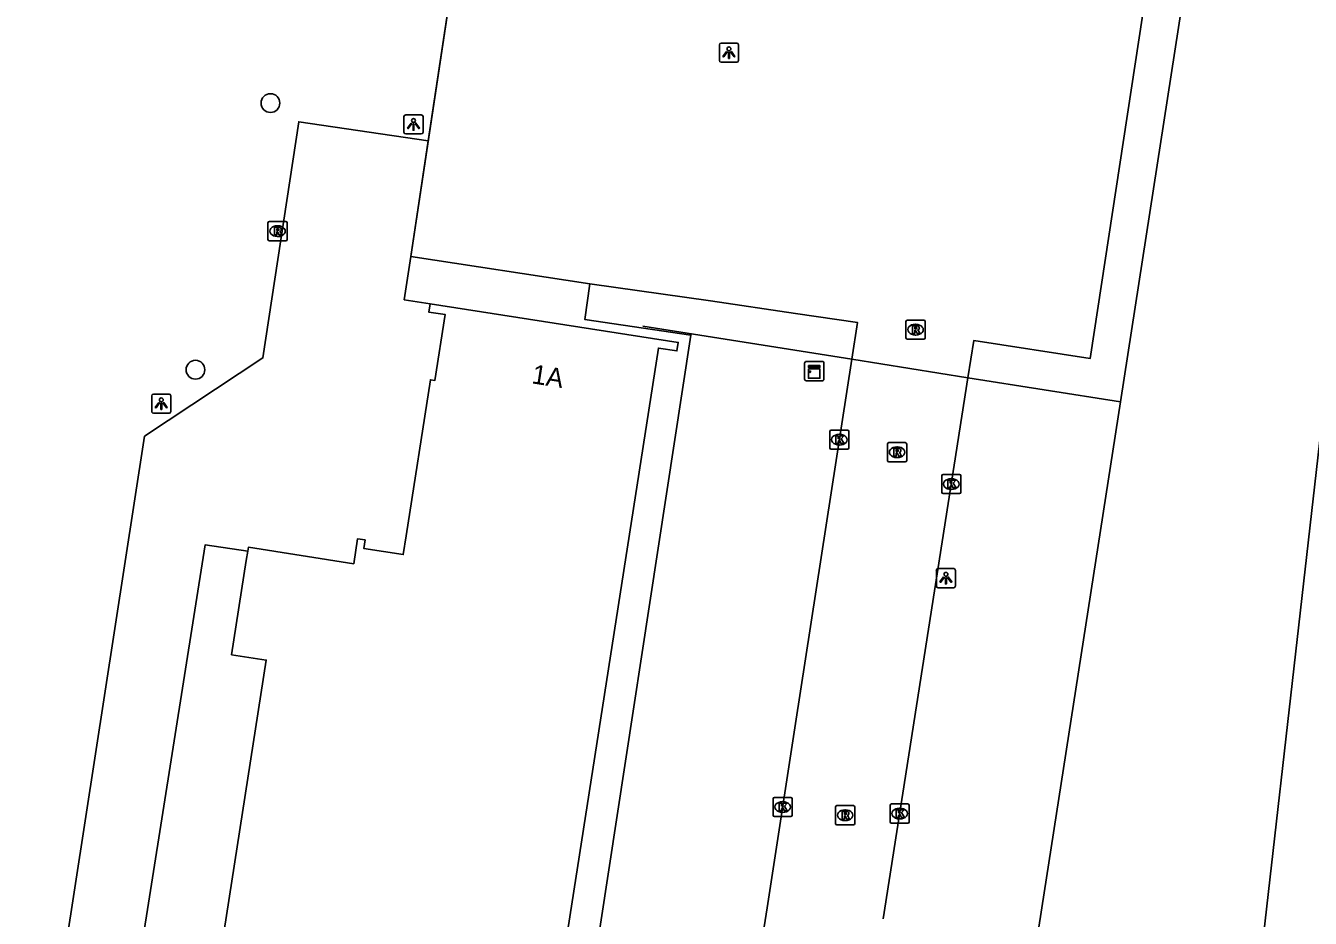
# Model space of a CAD drawing. Extents: x 161094 to 161705, y 379509 to 380907.
# Drawn here: x 161459.9 to 161526.8, y 380785 to 380831.5 of the extents above; entities that cross this region are included whole.
import ezdxf

# ---------------------------------------------------------------- set-up
doc = ezdxf.new("R2010")
doc.units = 0
for name, color, linetype in [('IMGEO_Boom', 7, 'Continuous'), ('IMGEO_Grasland_overig', 7, 'Continuous'), ('IMGEO_Groenvoorziening', 7, 'Continuous'), ('IMGEO_Hek', 7, 'Continuous'), ('IMGEO_Kast', 7, 'Continuous'), ('IMGEO_Kolk', 7, 'Continuous'), ('IMGEO_Lichtpunt', 7, 'Continuous'), ('IMGEO_Pand', 7, 'Continuous'), ('IMGEO_Pand_nummerreeks', 7, 'Continuous'), ('IMGEO_Pand_vergunning_verleend', 7, 'Continuous'), ('IMGEO_Rijbaan_lokaal_open', 7, 'Continuous'), ('IMGEO_Rioolput', 7, 'Continuous')]:
    doc.layers.add(name, color=color, linetype=linetype)

msp = doc.modelspace()

# ---------------------------------------------------------------- linework, layer by layer
at = {"layer": 'IMGEO_Boom'}
for centre in [(161472.664, 380827.464), (161468.76, 380813.578)]:
    msp.add_circle(centre, 0.489, dxfattribs=at)
at = {"layer": 'IMGEO_Grasland_overig'}
for points in [[(161516.913, 380811.905), (161521.086, 380838.815), (161601.047, 380825.222), (161596.254, 380793.968)], [(161489.288, 380818.046), (161489.039, 380816.188), (161494.551, 380815.379), (161489.009, 380779.266), (161488.373, 380779.362)], [(161516.913, 380811.905), (161512.549, 380783.771)]]:
    msp.add_lwpolyline(points, dxfattribs=at)
at = {"layer": 'IMGEO_Groenvoorziening'}
msp.add_lwpolyline([(161508.972, 380813.163), (161516.913, 380811.905)], dxfattribs=at)
at = {"layer": 'IMGEO_Hek'}
for points in [[(161483.811, 380844.913), (161479.969, 380819.467)], [(161479.969, 380819.467), (161479.63, 380817.221), (161480.975, 380817.011)], [(161492.055, 380815.844), (161502.924, 380814.122)], [(161502.924, 380814.122), (161508.972, 380813.163)]]:
    msp.add_lwpolyline(points, dxfattribs=at)
at = {"layer": 'IMGEO_Kast'}
for p, q in [((161500.475, 380813.08), (161500.475, 380813.921)), ((161500.475, 380813.921), (161500.475, 380813.08)), ((161500.55, 380814.005), (161501.391, 380814.005)), ((161501.391, 380814.005), (161500.55, 380814.005)), ((161501.475, 380813.93), (161501.475, 380813.089)), ((161501.475, 380813.089), (161501.475, 380813.93)), ((161501.4, 380813.005), (161500.559, 380813.005)), ((161500.559, 380813.005), (161501.4, 380813.005))]:
    msp.add_line(p, q, dxfattribs=at)
for points in [[(161500.67, 380813.795), (161501.27, 380813.795), (161501.27, 380813.71), (161500.67, 380813.71), (161500.67, 380813.795)], [(161500.67, 380813.62), (161501.27, 380813.62), (161501.27, 380813.131), (161500.67, 380813.131), (161500.67, 380813.62)]]:
    msp.add_lwpolyline(points, dxfattribs=at)
msp.add_circle((161500.754, 380813.469), 0.0377, dxfattribs=at)
for centre, start, end in [((161500.553, 380813.927), 92.4484, 184.28452), ((161500.553, 380813.927), 92.4484, 184.28452), ((161501.397, 380813.927), 2.4484, 94.28452), ((161501.397, 380813.927), 2.4484, 94.28452), ((161500.553, 380813.083), 182.4484, 274.28452), ((161500.553, 380813.083), 182.4484, 274.28452), ((161501.397, 380813.083), 272.4484, 4.28452), ((161501.397, 380813.083), 272.4484, 4.28452)]:
    msp.add_arc(centre, 0.0779, start, end, dxfattribs=at)
at = {"layer": 'IMGEO_Kolk'}
for p, q in [((161501.781, 380809.508), (161501.781, 380810.36)), ((161501.856, 380810.434), (161502.708, 380810.434)), ((161502.269, 380810.214), (161502.294, 380810.214)), ((161502.782, 380810.36), (161502.782, 380809.508)), ((161502.708, 380809.434), (161501.856, 380809.434)), ((161502.292, 380809.654), (161502.267, 380809.654)), ((161507.61, 380807.198), (161507.61, 380808.05)), ((161507.685, 380808.124), (161508.537, 380808.124)), ((161508.611, 380808.05), (161508.611, 380807.198)), ((161508.098, 380807.904), (161508.123, 380807.904)), ((161508.537, 380807.124), (161507.685, 380807.124)), ((161508.121, 380807.344), (161508.096, 380807.344)), ((161498.828, 380790.378), (161498.828, 380791.23)), ((161498.903, 380791.304), (161499.755, 380791.304)), ((161499.316, 380791.084), (161499.341, 380791.084)), ((161499.829, 380791.23), (161499.829, 380790.378)), ((161504.921, 380790.037), (161504.921, 380790.889)), ((161504.996, 380790.963), (161505.848, 380790.963)), ((161505.409, 380790.743), (161505.434, 380790.743)), ((161505.922, 380790.889), (161505.922, 380790.037)), ((161499.755, 380790.304), (161498.903, 380790.304)), ((161499.339, 380790.524), (161499.314, 380790.524)), ((161505.432, 380790.183), (161505.407, 380790.183)), ((161505.848, 380789.963), (161504.996, 380789.963))]:
    msp.add_line(p, q, dxfattribs=at)
for points in [[(161501.781, 380809.508), (161501.781, 380810.36)], [(161501.856, 380810.434), (161502.708, 380810.434)], [(161502.102, 380810.134), (161502.225, 380810.134), (161502.225, 380809.983), (161502.355, 380810.134), (161502.519, 380810.134), (161502.373, 380809.983), (161502.526, 380809.734), (161502.374, 380809.734), (161502.289, 380809.898), (161502.225, 380809.831), (161502.225, 380809.734), (161502.102, 380809.734), (161502.102, 380810.134)], [(161502.782, 380810.36), (161502.782, 380809.508)], [(161502.708, 380809.434), (161501.856, 380809.434)], [(161507.61, 380807.198), (161507.61, 380808.05)], [(161507.685, 380808.124), (161508.537, 380808.124)], [(161508.611, 380808.05), (161508.611, 380807.198)], [(161507.931, 380807.824), (161508.054, 380807.824), (161508.054, 380807.673), (161508.184, 380807.824), (161508.348, 380807.824), (161508.202, 380807.673), (161508.355, 380807.424), (161508.203, 380807.424), (161508.118, 380807.588), (161508.054, 380807.521), (161508.054, 380807.424), (161507.931, 380807.424), (161507.931, 380807.824)], [(161508.537, 380807.124), (161507.685, 380807.124)], [(161498.828, 380790.378), (161498.828, 380791.23)], [(161498.903, 380791.304), (161499.755, 380791.304)], [(161499.149, 380791.004), (161499.272, 380791.004), (161499.272, 380790.853), (161499.402, 380791.004), (161499.566, 380791.004), (161499.42, 380790.853), (161499.573, 380790.604), (161499.421, 380790.604), (161499.336, 380790.768), (161499.272, 380790.701), (161499.272, 380790.604), (161499.149, 380790.604), (161499.149, 380791.004)], [(161499.829, 380791.23), (161499.829, 380790.378)], [(161504.921, 380790.037), (161504.921, 380790.889)], [(161504.996, 380790.963), (161505.848, 380790.963)], [(161505.242, 380790.663), (161505.365, 380790.663), (161505.365, 380790.512), (161505.495, 380790.663), (161505.659, 380790.663), (161505.513, 380790.512), (161505.666, 380790.263), (161505.514, 380790.263), (161505.429, 380790.427), (161505.365, 380790.36), (161505.365, 380790.263), (161505.242, 380790.263), (161505.242, 380790.663)], [(161505.922, 380790.889), (161505.922, 380790.037)], [(161499.755, 380790.304), (161498.903, 380790.304)], [(161505.848, 380789.963), (161504.996, 380789.963)]]:
    msp.add_lwpolyline(points, dxfattribs=at)
for centre, start, end in [((161501.858, 380810.358), 91.55205, 178.44795), ((161501.858, 380810.358), 91.55205, 178.44795), ((161502.706, 380810.358), 1.55205, 88.44795), ((161502.706, 380810.358), 1.55205, 88.44795), ((161501.858, 380809.51), 181.55205, 268.44795), ((161501.858, 380809.51), 181.55205, 268.44795), ((161502.706, 380809.51), 271.55205, 358.44795), ((161502.706, 380809.51), 271.55205, 358.44795), ((161507.687, 380808.048), 91.55205, 178.44795), ((161507.687, 380808.048), 91.55205, 178.44795), ((161508.535, 380808.048), 1.55205, 88.44795), ((161508.535, 380808.048), 1.55205, 88.44795), ((161507.687, 380807.2), 181.55205, 268.44795), ((161507.687, 380807.2), 181.55205, 268.44795), ((161508.535, 380807.2), 271.55205, 358.44795), ((161508.535, 380807.2), 271.55205, 358.44795), ((161498.905, 380791.228), 91.55205, 178.44795), ((161498.905, 380791.228), 91.55205, 178.44795), ((161499.753, 380791.228), 1.55205, 88.44795), ((161499.753, 380791.228), 1.55205, 88.44795), ((161504.998, 380790.887), 91.55205, 178.44795), ((161504.998, 380790.887), 91.55205, 178.44795), ((161505.846, 380790.887), 1.55205, 88.44795), ((161505.846, 380790.887), 1.55205, 88.44795), ((161498.905, 380790.38), 181.55205, 268.44795), ((161498.905, 380790.38), 181.55205, 268.44795), ((161499.753, 380790.38), 271.55205, 358.44795), ((161499.753, 380790.38), 271.55205, 358.44795), ((161504.998, 380790.039), 181.55205, 268.44795), ((161504.998, 380790.039), 181.55205, 268.44795), ((161505.846, 380790.039), 271.55205, 358.44795), ((161505.846, 380790.039), 271.55205, 358.44795)]:
    msp.add_arc(centre, 0.0765, start, end, dxfattribs=at)
for centre, major_axis, ratio, start_param, end_param in [((161502.268, 380809.934), (-0.387, 0.002), 0.722429, 4.712389, 7.853982), ((161502.293, 380809.934), (-0.39, 0.002), 0.717154, 1.570796, 4.712389), ((161508.097, 380807.624), (-0.387, 0.002), 0.722429, 4.712389, 7.853982), ((161508.122, 380807.624), (-0.39, 0.002), 0.717154, 1.570796, 4.712389), ((161499.315, 380790.804), (-0.387, 0.002), 0.722429, 4.712389, 7.853982), ((161499.34, 380790.804), (-0.39, 0.002), 0.717154, 1.570796, 4.712389), ((161505.408, 380790.463), (-0.387, 0.002), 0.722429, 4.712389, 7.853982), ((161505.433, 380790.463), (-0.39, 0.002), 0.717154, 1.570796, 4.712389)]:
    msp.add_ellipse(centre, major_axis=major_axis, ratio=ratio, start_param=start_param, end_param=end_param, dxfattribs=at)
at = {"layer": 'IMGEO_Lichtpunt'}
for p, q in [((161496.036, 380830.492), (161496.036, 380829.685)), ((161496.036, 380830.492), (161496.036, 380829.685)), ((161496.938, 380830.587), (161496.13, 380830.587)), ((161496.938, 380830.587), (161496.13, 380830.587)), ((161497.032, 380829.685), (161497.032, 380830.492)), ((161497.032, 380829.685), (161497.032, 380830.492)), ((161496.13, 380829.591), (161496.938, 380829.591)), ((161496.13, 380829.591), (161496.938, 380829.591)), ((161479.614, 380826.759), (161479.614, 380825.952)), ((161479.614, 380826.759), (161479.614, 380825.952)), ((161480.516, 380826.854), (161479.708, 380826.854)), ((161480.516, 380826.854), (161479.708, 380826.854)), ((161480.61, 380825.952), (161480.61, 380826.759)), ((161480.61, 380825.952), (161480.61, 380826.759)), ((161479.708, 380825.858), (161480.516, 380825.858)), ((161479.708, 380825.858), (161480.516, 380825.858)), ((161466.483, 380812.212), (161466.483, 380811.405)), ((161466.483, 380812.212), (161466.483, 380811.405)), ((161467.385, 380812.307), (161466.577, 380812.307)), ((161467.385, 380812.307), (161466.577, 380812.307)), ((161467.479, 380811.405), (161467.479, 380812.212)), ((161467.479, 380811.405), (161467.479, 380812.212)), ((161466.577, 380811.311), (161467.385, 380811.311)), ((161466.577, 380811.311), (161467.385, 380811.311)), ((161507.331, 380803.126), (161507.331, 380802.319)), ((161507.331, 380803.126), (161507.331, 380802.319)), ((161508.233, 380803.221), (161507.425, 380803.221)), ((161508.233, 380803.221), (161507.425, 380803.221)), ((161508.327, 380802.319), (161508.327, 380803.126)), ((161508.327, 380802.319), (161508.327, 380803.126)), ((161507.425, 380802.225), (161508.233, 380802.225)), ((161507.425, 380802.225), (161508.233, 380802.225))]:
    msp.add_line(p, q, dxfattribs=at)
for points in [[(161496.41, 380830.156), (161496.449, 380830.128), (161496.261, 380829.866), (161496.223, 380829.893), (161496.41, 380830.156)], [(161496.512, 380830.108), (161496.559, 380830.108), (161496.559, 380829.786), (161496.512, 380829.786), (161496.512, 380830.108)], [(161496.622, 380830.128), (161496.66, 380830.155), (161496.847, 380829.893), (161496.808, 380829.865), (161496.622, 380830.128)], [(161479.988, 380826.423), (161480.027, 380826.395), (161479.839, 380826.133), (161479.801, 380826.16), (161479.988, 380826.423)], [(161480.09, 380826.375), (161480.137, 380826.375), (161480.137, 380826.053), (161480.09, 380826.053), (161480.09, 380826.375)], [(161480.2, 380826.395), (161480.238, 380826.422), (161480.425, 380826.16), (161480.386, 380826.132), (161480.2, 380826.395)], [(161466.857, 380811.876), (161466.896, 380811.848), (161466.708, 380811.586), (161466.67, 380811.613), (161466.857, 380811.876)], [(161466.959, 380811.828), (161467.006, 380811.828), (161467.006, 380811.506), (161466.959, 380811.506), (161466.959, 380811.828)], [(161467.069, 380811.848), (161467.107, 380811.875), (161467.294, 380811.613), (161467.255, 380811.585), (161467.069, 380811.848)], [(161507.705, 380802.79), (161507.744, 380802.762), (161507.556, 380802.5), (161507.518, 380802.527), (161507.705, 380802.79)], [(161507.807, 380802.742), (161507.854, 380802.742), (161507.854, 380802.42), (161507.807, 380802.42), (161507.807, 380802.742)], [(161507.917, 380802.762), (161507.955, 380802.789), (161508.142, 380802.527), (161508.103, 380802.499), (161507.917, 380802.762)]]:
    msp.add_lwpolyline(points, dxfattribs=at)
for centre in [(161496.535, 380830.29), (161480.113, 380826.557), (161466.982, 380812.01), (161507.83, 380802.924)]:
    msp.add_circle(centre, 0.0994, dxfattribs=at)
for centre, start, end in [((161496.13, 380830.492), 90, 180), ((161496.13, 380830.492), 90, 180), ((161496.938, 380830.492), 0, 90), ((161496.938, 380830.492), 0, 90), ((161496.13, 380829.685), 180, 270), ((161496.13, 380829.685), 180, 270), ((161496.938, 380829.685), 270, 0), ((161496.938, 380829.685), 270, 360), ((161479.708, 380826.759), 90, 180), ((161479.708, 380826.759), 90, 180), ((161480.516, 380826.759), 0, 90), ((161480.516, 380826.759), 0, 90), ((161479.708, 380825.952), 180, 270), ((161479.708, 380825.952), 180, 270), ((161480.516, 380825.952), 270, 0), ((161480.516, 380825.952), 270, 360), ((161466.577, 380812.212), 90, 180), ((161466.577, 380812.212), 90, 180), ((161467.385, 380812.212), 0, 90), ((161467.385, 380812.212), 0, 90), ((161466.577, 380811.405), 180, 270), ((161466.577, 380811.405), 180, 270), ((161467.385, 380811.405), 270, 0), ((161467.385, 380811.405), 270, 360), ((161507.425, 380803.126), 90, 180), ((161507.425, 380803.126), 90, 180), ((161508.233, 380803.126), 0, 90), ((161508.233, 380803.126), 0, 90), ((161507.425, 380802.319), 180, 270), ((161507.425, 380802.319), 180, 270), ((161508.233, 380802.319), 270, 0), ((161508.233, 380802.319), 270, 360)]:
    msp.add_arc(centre, 0.0946, start, end, dxfattribs=at)
at = {"layer": 'IMGEO_Pand'}
for points in [[(161471.482, 380804.13), (161471.513, 380804.33), (161476.997, 380803.476), (161477.199, 380804.771), (161477.588, 380804.71), (161477.52, 380804.268), (161479.576, 380803.948), (161479.729, 380804.929), (161480.995, 380813.059), (161481.228, 380813.023), (161481.762, 380816.45), (161480.909, 380816.583), (161480.975, 380817.011)], [(161488.373, 380779.362), (161488.443, 380779.809), (161487.449, 380779.964), (161492.859, 380814.704), (161493.827, 380814.553), (161493.896, 380814.998), (161480.975, 380817.011)], [(161479.562, 380780.734), (161476.814, 380781.162), (161476.589, 380779.719), (161477.75, 380779.538), (161477.168, 380775.804), (161467.337, 380777.335), (161467.919, 380781.072), (161469.697, 380780.795), (161472.447, 380798.453), (161470.641, 380798.735), (161471.406, 380803.645), (161471.482, 380804.13)]]:
    msp.add_lwpolyline(points, dxfattribs=at)
at = {"layer": 'IMGEO_Pand_vergunning_verleend'}
msp.add_lwpolyline([(161523.106, 380773.117), (161527.36, 380810.515), (161542.271, 380808.163), (161541.03, 380800.291), (161538.939, 380800.621), (161535.649, 380771.69), (161523.106, 380773.117)], dxfattribs=at)
at = {"layer": 'IMGEO_Rijbaan_lokaal_open'}
for points in [[(161514.151, 380847.032), (161513.175, 380840.578), (161519.233, 380839.628), (161515.332, 380814.159), (161509.275, 380815.096), (161508.972, 380813.163)], [(161480.879, 380825.492), (161483.811, 380844.913)], [(161480.879, 380825.492), (161474.136, 380826.491), (161472.272, 380814.194), (161466.099, 380810.112), (161459.922, 380770.043)], [(161479.969, 380819.467), (161480.879, 380825.492)], [(161480.975, 380817.011), (161479.63, 380817.221), (161479.969, 380819.467)], [(161489.288, 380818.046), (161479.969, 380819.467)], [(161502.924, 380814.122), (161503.22, 380816.04), (161500, 380816.511), (161495.578, 380817.158), (161489.288, 380818.046)], [(161502.924, 380814.122), (161500, 380795.153), (161498.521, 380785.559), (161496.279, 380771.409)], [(161508.972, 380813.163), (161502.924, 380814.122)], [(161504.561, 380784.974), (161508.972, 380813.163)], [(161464.799, 380776.254), (161469.257, 380804.457), (161471.482, 380804.13)]]:
    msp.add_lwpolyline(points, dxfattribs=at)
at = {"layer": 'IMGEO_Rioolput'}
for p, q in [((161472.535, 380820.368), (161472.535, 380821.22)), ((161472.61, 380821.294), (161473.462, 380821.294)), ((161473.023, 380821.074), (161473.048, 380821.074)), ((161473.536, 380821.22), (161473.536, 380820.368)), ((161473.462, 380820.294), (161472.61, 380820.294)), ((161473.046, 380820.514), (161473.021, 380820.514)), ((161505.75, 380815.238), (161505.75, 380816.09)), ((161505.825, 380816.164), (161506.677, 380816.164)), ((161506.751, 380816.09), (161506.751, 380815.238)), ((161506.261, 380815.384), (161506.236, 380815.384)), ((161506.238, 380815.944), (161506.263, 380815.944)), ((161506.677, 380815.164), (161505.825, 380815.164)), ((161504.787, 380808.856), (161504.787, 380809.708)), ((161504.862, 380809.782), (161505.714, 380809.782)), ((161505.275, 380809.562), (161505.3, 380809.562)), ((161505.788, 380809.708), (161505.788, 380808.856)), ((161505.714, 380808.782), (161504.862, 380808.782)), ((161505.298, 380809.002), (161505.273, 380809.002)), ((161502.083, 380789.95), (161502.083, 380790.802)), ((161502.158, 380790.876), (161503.01, 380790.876)), ((161502.571, 380790.656), (161502.596, 380790.656)), ((161503.084, 380790.802), (161503.084, 380789.95)), ((161502.594, 380790.096), (161502.569, 380790.096)), ((161503.01, 380789.876), (161502.158, 380789.876))]:
    msp.add_line(p, q, dxfattribs=at)
for points in [[(161472.535, 380820.368), (161472.535, 380821.22)], [(161472.61, 380821.294), (161473.462, 380821.294)], [(161473.124, 380820.992), (161472.872, 380820.994), (161472.872, 380820.594)], [(161472.872, 380820.594), (161472.996, 380820.594), (161472.996, 380820.756), (161473.007, 380820.756)], [(161473.05, 380820.913), (161472.996, 380820.913), (161472.996, 380820.832)], [(161472.996, 380820.832), (161473.048, 380820.832)], [(161473.536, 380821.22), (161473.536, 380820.368)], [(161473.462, 380820.294), (161472.61, 380820.294)], [(161473.054, 380820.727), (161473.125, 380820.594), (161473.265, 380820.594), (161473.2, 380820.72)], [(161505.75, 380815.238), (161505.75, 380816.09)], [(161505.825, 380816.164), (161506.677, 380816.164)], [(161506.751, 380816.09), (161506.751, 380815.238)], [(161506.339, 380815.862), (161506.087, 380815.864), (161506.087, 380815.464)], [(161506.087, 380815.464), (161506.211, 380815.464), (161506.211, 380815.626), (161506.222, 380815.626)], [(161506.265, 380815.783), (161506.211, 380815.783), (161506.211, 380815.702)], [(161506.211, 380815.702), (161506.263, 380815.702)], [(161506.269, 380815.597), (161506.34, 380815.464), (161506.48, 380815.464), (161506.415, 380815.59)], [(161506.677, 380815.164), (161505.825, 380815.164)], [(161504.787, 380808.856), (161504.787, 380809.708)], [(161504.862, 380809.782), (161505.714, 380809.782)], [(161505.376, 380809.48), (161505.124, 380809.482), (161505.124, 380809.082)], [(161505.302, 380809.401), (161505.248, 380809.401), (161505.248, 380809.32)], [(161505.788, 380809.708), (161505.788, 380808.856)], [(161505.714, 380808.782), (161504.862, 380808.782)], [(161505.124, 380809.082), (161505.248, 380809.082), (161505.248, 380809.244), (161505.259, 380809.244)], [(161505.248, 380809.32), (161505.3, 380809.32)], [(161505.306, 380809.215), (161505.377, 380809.082), (161505.517, 380809.082), (161505.452, 380809.208)], [(161502.083, 380789.95), (161502.083, 380790.802)], [(161502.158, 380790.876), (161503.01, 380790.876)], [(161503.084, 380790.802), (161503.084, 380789.95)], [(161502.672, 380790.574), (161502.42, 380790.576), (161502.42, 380790.176)], [(161502.42, 380790.176), (161502.544, 380790.176), (161502.544, 380790.338), (161502.555, 380790.338)], [(161502.598, 380790.495), (161502.544, 380790.495), (161502.544, 380790.414)], [(161502.544, 380790.414), (161502.596, 380790.414)], [(161502.602, 380790.309), (161502.673, 380790.176), (161502.813, 380790.176), (161502.748, 380790.302)], [(161503.01, 380789.876), (161502.158, 380789.876)]]:
    msp.add_lwpolyline(points, dxfattribs=at)
for centre, radius, start, end in [((161472.612, 380821.218), 0.0765, 91.55205, 178.44795), ((161472.612, 380821.218), 0.0765, 91.55205, 178.44795), ((161473.006, 380820.703), 0.0533, 26.02933, 88.69889), ((161473.032, 380821.021), 0.19, 274.7715, 282.96867), ((161473.056, 380820.817), 0.0964, 77.00612, 93.18647), ((161473.07, 380820.874), 0.0378, 276.66336, 79.67722), ((161473.123, 380820.882), 0.109, 350.36119, 89.41601), ((161473.121, 380820.882), 0.112, 277.58423, 350.98172), ((161473.105, 380820.667), 0.108, 29.51342, 73.79051), ((161473.46, 380821.218), 0.0765, 1.55205, 88.44795), ((161473.46, 380821.218), 0.0765, 1.55205, 88.44795), ((161472.612, 380820.37), 0.0765, 181.55205, 268.44795), ((161472.612, 380820.37), 0.0765, 181.55205, 268.44795), ((161473.46, 380820.37), 0.0765, 271.55205, 358.44795), ((161473.46, 380820.37), 0.0765, 271.55205, 358.44795), ((161505.827, 380816.088), 0.0765, 91.55205, 178.44795), ((161505.827, 380816.088), 0.0765, 91.55205, 178.44795), ((161506.675, 380816.088), 0.0765, 1.55205, 88.44795), ((161506.675, 380816.088), 0.0765, 1.55205, 88.44795), ((161506.221, 380815.573), 0.0533, 26.02933, 88.69889), ((161506.247, 380815.891), 0.19, 274.7715, 282.96867), ((161506.271, 380815.687), 0.0964, 77.00612, 93.18647), ((161506.285, 380815.744), 0.0378, 276.66336, 79.67722), ((161506.338, 380815.752), 0.109, 350.36119, 89.41601), ((161506.336, 380815.752), 0.112, 277.58423, 350.98172), ((161506.32, 380815.537), 0.108, 29.51342, 73.79051), ((161505.827, 380815.24), 0.0765, 181.55205, 268.44795), ((161505.827, 380815.24), 0.0765, 181.55205, 268.44795), ((161506.675, 380815.24), 0.0765, 271.55205, 358.44795), ((161506.675, 380815.24), 0.0765, 271.55205, 358.44795), ((161504.864, 380809.706), 0.0765, 91.55205, 178.44795), ((161504.864, 380809.706), 0.0765, 91.55205, 178.44795), ((161505.308, 380809.305), 0.0964, 77.00612, 93.18647), ((161505.322, 380809.362), 0.0378, 276.66336, 79.67722), ((161505.375, 380809.37), 0.109, 350.36119, 89.41601), ((161505.712, 380809.706), 0.0765, 1.55205, 88.44795), ((161505.712, 380809.706), 0.0765, 1.55205, 88.44795), ((161504.864, 380808.858), 0.0765, 181.55205, 268.44795), ((161504.864, 380808.858), 0.0765, 181.55205, 268.44795), ((161505.258, 380809.191), 0.0533, 26.02933, 88.69889), ((161505.284, 380809.509), 0.19, 274.7715, 282.96867), ((161505.373, 380809.37), 0.112, 277.58423, 350.98172), ((161505.357, 380809.155), 0.108, 29.51342, 73.79051), ((161505.712, 380808.858), 0.0765, 271.55205, 358.44795), ((161505.712, 380808.858), 0.0765, 271.55205, 358.44795), ((161502.16, 380790.8), 0.0765, 91.55205, 178.44795), ((161502.16, 380790.8), 0.0765, 91.55205, 178.44795), ((161503.008, 380790.8), 0.0765, 1.55205, 88.44795), ((161503.008, 380790.8), 0.0765, 1.55205, 88.44795), ((161502.554, 380790.285), 0.0533, 26.02933, 88.69889), ((161502.58, 380790.603), 0.19, 274.7715, 282.96867), ((161502.604, 380790.399), 0.0964, 77.00612, 93.18647), ((161502.618, 380790.456), 0.0378, 276.66336, 79.67722), ((161502.671, 380790.464), 0.109, 350.36119, 89.41601), ((161502.669, 380790.464), 0.112, 277.58423, 350.98172), ((161502.653, 380790.249), 0.108, 29.51342, 73.79051), ((161502.16, 380789.952), 0.0765, 181.55205, 268.44795), ((161502.16, 380789.952), 0.0765, 181.55205, 268.44795), ((161503.008, 380789.952), 0.0765, 271.55205, 358.44795), ((161503.008, 380789.952), 0.0765, 271.55205, 358.44795)]:
    msp.add_arc(centre, radius, start, end, dxfattribs=at)
for centre, major_axis, ratio, start_param, end_param in [((161473.022, 380820.794), (-0.387, 0.002), 0.722429, 4.712389, 7.853982), ((161473.047, 380820.794), (-0.39, 0.002), 0.717154, 1.570796, 4.712389), ((161506.237, 380815.664), (-0.387, 0.002), 0.722429, 4.712389, 7.853982), ((161506.262, 380815.664), (-0.39, 0.002), 0.717154, 1.570796, 4.712389), ((161505.274, 380809.282), (-0.387, 0.002), 0.722429, 4.712389, 7.853982), ((161505.299, 380809.282), (-0.39, 0.002), 0.717154, 1.570796, 4.712389), ((161502.57, 380790.376), (-0.387, 0.002), 0.722429, 4.712389, 7.853982), ((161502.595, 380790.376), (-0.39, 0.002), 0.717154, 1.570796, 4.712389)]:
    msp.add_ellipse(centre, major_axis=major_axis, ratio=ratio, start_param=start_param, end_param=end_param, dxfattribs=at)

# ---------------------------------------------------------------- texts
at = {"layer": 'IMGEO_Pand_nummerreeks'}
msp.add_text('1A', height=1, rotation=351.14207, dxfattribs=at).set_placement((161486.226, 380812.873))

doc.saveas('drawing.dxf')
